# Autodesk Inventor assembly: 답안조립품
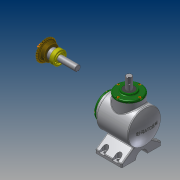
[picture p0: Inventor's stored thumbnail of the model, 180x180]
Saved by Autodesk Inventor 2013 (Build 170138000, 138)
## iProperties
Created: 2017-04
Part Number: 답안조립품
Document SubType Name: Assembly
Designer: Administrator
Author: Administrator
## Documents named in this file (14)
- C:\Users\Administrator\Desktop\470408V1006\답안조립품.iam
- C:\Users\Administrator\Desktop\470408V1006\본체.ipt
- C:\Users\Administrator\Desktop\470408V1006\메인 베벨기어.ipt
- C:\Users\Administrator\Desktop\470408V1006\메인 축.ipt
- 메인 축.ipt
- C:\Users\Administrator\Desktop\470408V1006\베어링 6203.ipt
- C:\Users\Administrator\Desktop\470408V1006\볼트 M4.ipt
- C:\Users\Administrator\Desktop\470408V1006\서브 베벨기어.ipt
- C:\Users\Administrator\Desktop\470408V1006\서브 축.ipt
- 서브 축.ipt
- C:\Users\Administrator\Desktop\470408V1006\오일실 17 32 8.ipt
- C:\Users\Administrator\Desktop\470408V1006\커버.ipt
- C:\Users\Administrator\Desktop\470408V1006\키 4x4.ipt
- C:\Users\Administrator\Desktop\470408V1006\키 5x5.ipt
